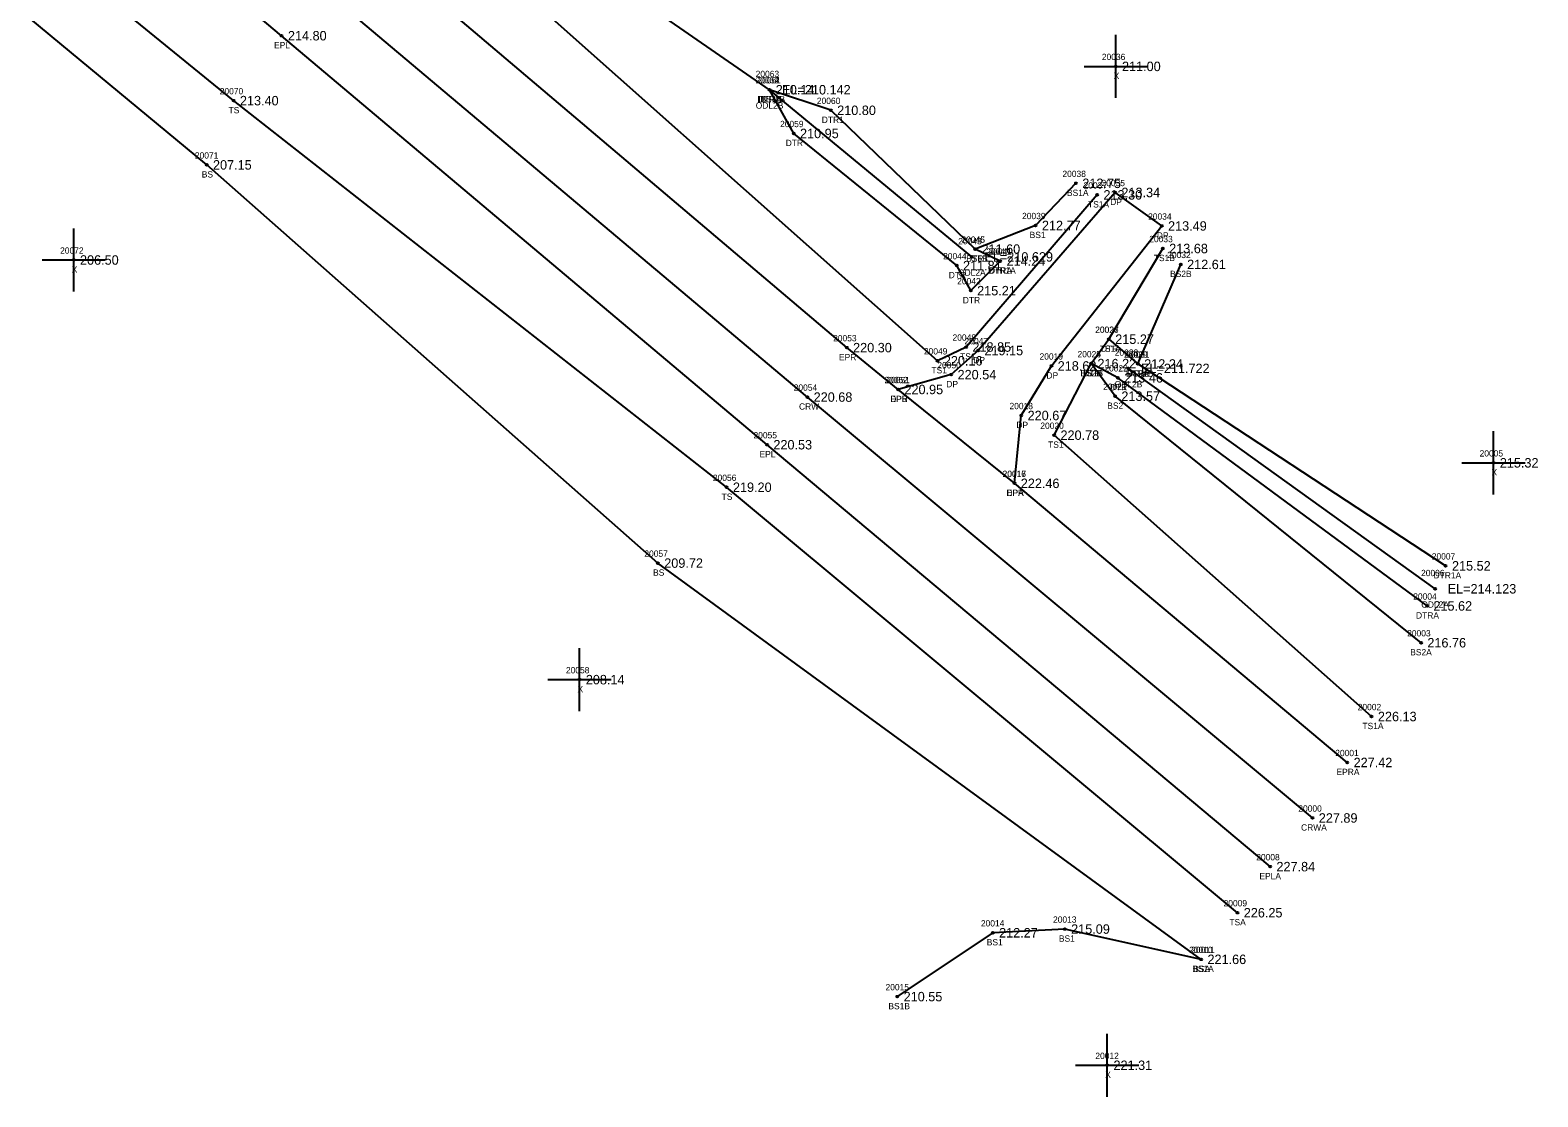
# Model space of a CAD drawing. Extents: x 2260230 to 2261304, y 1064626 to 1065587.
# Drawn here: x 2260916.2 to 2261155.1, y 1064774.4 to 1064943.4 of the extents above; entities that cross this region are included whole.
import ezdxf

# ---------------------------------------------------------------- set-up
doc = ezdxf.new("R2010")
doc.units = 0
for name, color, linetype in [('RD_DTM_BkLn1', 7, 'Continuous'), ('RD_DTM_BkLn2', 7, 'Continuous'), ('RD_DTM_BkLn_txCode', 7, 'Continuous'), ('RD_EX_Driveway', 7, 'Continuous'), ('RD_EX_Driveway_txCode', 7, 'Continuous'), ('RD_EX_H2O', 7, 'Continuous'), ('RD_EX_H2O_txCode', 7, 'Continuous'), ('RD_EX_Misc', 7, 'Continuous'), ('RD_EX_Misc_txCode', 7, 'Continuous'), ('RD_EX_Road', 7, 'Continuous'), ('RD_EX_Road_txCode', 7, 'Continuous'), ('RD_EX_TX_Driveway_ELEV', 7, 'Continuous'), ('RD_EX_TX_H2O_ELEV', 7, 'Continuous'), ('RD_EX_TX_Misc_ELEV', 7, 'Continuous'), ('RD_EX_TX_Road_ELEV', 7, 'Continuous'), ('RD_HC_Survey_ELEV', 7, 'Continuous'), ('RD_HC_Survey_txCode', 7, 'Continuous'), ('RD_SMD_Locator', 7, 'Continuous')]:
    doc.layers.add(name, color=color, linetype=linetype)

msp = doc.modelspace()

# ---------------------------------------------------------------- linework, layer by layer
at = {"layer": 'RD_DTM_BkLn1'}
msp.add_lwpolyline([(2261119.39, 1064818.57), (2261039.33, 1064885.27), (2260966.22, 1064946.78), (2260891.14, 1065010.3), (2260825.73, 1065065.53)], dxfattribs=at)
at = {"layer": 'RD_DTM_BkLn2'}
for p, q in [((2261087.13, 1064894.44), (2261095.68, 1064908.81)), ((2261091.72, 1064890.51), (2261098.52, 1064906.29))]:
    msp.add_line(p, q, dxfattribs=at)
for points in [[(2261107.5, 1064803.56), (2261026.54, 1064870.98), (2260948.4, 1064932.24), (2260874.38, 1064992.47), (2260842.04, 1065014.91), (2260817.83, 1065046.66), (2260820.04, 1065048.66), (2260815.22, 1065054.09)], [(2261101.75, 1064796.17), (2261015.65, 1064858.96), (2260944.13, 1064922.06), (2260868.1, 1064985.02), (2260817.12, 1065034.76), (2260812.18, 1065041.52), (2260806.25, 1065051.8)], [(2261085.26, 1064917.31), (2261064.5, 1064893.2), (2261059.96, 1064891.02), (2260979.07, 1064962.89), (2260952.45, 1064989.91), (2260955.15, 1064997.29), (2260970.81, 1065018.43)], [(2261033.32, 1064933.97), (2260984.04, 1064968.09), (2260958.89, 1064995.55), (2260960.53, 1065000.94), (2260972.35, 1065016.34)], [(2261081.91, 1064919.14), (2261075.51, 1064912.46), (2261065.93, 1064908.72)], [(2261128.76, 1064834.65), (2261078.45, 1064879.23), (2261084.31, 1064890.57)], [(2261136.6, 1064846.34), (2261088.1, 1064885.41), (2261084.31, 1064890.57)], [(2261101.75, 1064796.17), (2261080.14, 1064800.97), (2261068.72, 1064800.38), (2261053.59, 1064790.26)]]:
    msp.add_lwpolyline(points, dxfattribs=at)
at = {"layer": 'RD_EX_Driveway'}
msp.add_lwpolyline([(2261072.16, 1064871.6), (2261073.24, 1064882.35), (2261078.01, 1064890.2), (2261095.5, 1064912.38), (2261088.11, 1064917.69), (2261066.4, 1064892.64), (2261062.14, 1064888.82), (2261053.72, 1064886.47)], dxfattribs=at)
at = {"layer": 'RD_EX_H2O'}
for p, q in [((2261065.39, 1064907.48), (2261033.32, 1064933.97)), ((2261138.82, 1064854.89), (2261090.21, 1064889.81)), ((2261140.5, 1064858.52), (2261091.72, 1064890.51))]:
    msp.add_line(p, q, dxfattribs=at)
for points in [[(2261069.9, 1064906.82), (2261065.24, 1064902.13), (2261063, 1064906.1), (2261037.17, 1064927.04), (2261033.32, 1064933.97)], [(2261069.9, 1064906.82), (2261065.93, 1064908.72), (2261043.06, 1064930.71), (2261033.32, 1064933.97)], [(2261137.56, 1064852.17), (2261088.56, 1064888.32), (2261084.31, 1064890.57), (2261087.13, 1064894.44), (2261091.72, 1064890.51)]]:
    msp.add_lwpolyline(points, dxfattribs=at)
at = {"layer": 'RD_EX_Misc'}
for p, q in [((2261088.2, 1064932.67), (2261088.2, 1064942.67)), ((2261083.2, 1064937.67), (2261093.2, 1064937.67)), ((2260923.05, 1064901.99), (2260923.05, 1064911.99)), ((2260918.05, 1064906.99), (2260928.05, 1064906.99)), ((2261148.08, 1064869.85), (2261148.08, 1064879.85)), ((2261143.08, 1064874.85), (2261153.08, 1064874.85)), ((2261003.22, 1064835.49), (2261003.22, 1064845.49)), ((2260998.22, 1064840.49), (2261008.22, 1064840.49)), ((2261086.85, 1064774.38), (2261086.85, 1064784.38)), ((2261081.85, 1064779.38), (2261091.85, 1064779.38))]:
    msp.add_line(p, q, dxfattribs=at)
at = {"layer": 'RD_EX_Road'}
for points in [[(2261124.91, 1064827.37), (2261072.16, 1064871.6), (2261053.72, 1064886.47), (2261045.58, 1064893.1), (2260972.89, 1064954.76), (2260940.74, 1064982.39), (2260933.33, 1064988.76), (2260898.06, 1065017.6), (2260832.89, 1065075.07)], [(2261112.68, 1064810.86), (2261032.95, 1064877.72), (2260956.01, 1064942.53), (2260884.53, 1065002.6), (2260818.6, 1065058.26)]]:
    msp.add_lwpolyline(points, dxfattribs=at)
at = {"layer": 'RD_SMD_Locator'}
for centre in [(2260956.01, 1064942.53), (2261088.2, 1064937.67), (2260948.4, 1064932.24), (2261033.32, 1064933.97), (2261033.32, 1064933.97), (2261033.32, 1064933.97), (2261033.32, 1064933.97), (2261043.06, 1064930.71), (2261037.17, 1064927.04), (2260944.13, 1064922.06), (2261081.91, 1064919.14), (2261085.26, 1064917.31), (2261088.11, 1064917.69), (2261075.51, 1064912.46), (2261095.5, 1064912.38), (2261065.93, 1064908.72), (2261065.93, 1064908.72), (2261095.68, 1064908.81), (2260923.05, 1064906.99), (2261063, 1064906.1), (2261065.39, 1064907.48), (2261069.9, 1064906.82), (2261069.9, 1064906.82), (2261098.52, 1064906.29), (2261065.24, 1064902.13), (2261087.13, 1064894.44), (2261087.13, 1064894.44), (2261045.58, 1064893.1), (2261064.5, 1064893.2), (2261066.4, 1064892.64), (2261059.96, 1064891.02), (2261078.01, 1064890.2), (2261084.31, 1064890.57), (2261084.31, 1064890.57), (2261084.31, 1064890.57), (2261090.21, 1064889.81), (2261091.72, 1064890.51), (2261091.72, 1064890.51), (2261091.72, 1064890.51), (2261062.14, 1064888.82), (2261088.56, 1064888.32), (2261039.33, 1064885.27), (2261053.72, 1064886.47), (2261053.72, 1064886.47), (2261088.1, 1064885.41), (2261073.24, 1064882.35), (2261032.95, 1064877.72), (2261078.45, 1064879.23), (2261148.08, 1064874.85), (2261026.54, 1064870.98), (2261072.16, 1064871.6), (2261072.16, 1064871.6), (2261015.65, 1064858.96), (2261140.5, 1064858.52), (2261138.82, 1064854.89), (2261137.56, 1064852.17), (2261136.6, 1064846.34), (2261003.22, 1064840.49), (2261128.76, 1064834.65), (2261124.91, 1064827.37), (2261119.39, 1064818.57), (2261112.68, 1064810.86), (2261107.5, 1064803.56), (2261080.14, 1064800.97), (2261068.72, 1064800.38), (2261101.75, 1064796.17), (2261101.75, 1064796.17), (2261053.59, 1064790.26), (2261086.85, 1064779.38)]:
    msp.add_circle(centre, 0.15, dxfattribs=at)

# ---------------------------------------------------------------- texts
at = {"layer": 'RD_DTM_BkLn_txCode'}
for s, p in [('20064', (2261031.14, 1064934.97)), ('20070', (2260946.2, 1064933.24)), ('BS1A', (2261031.89, 1064931.97)), ('TS', (2260947.6, 1064930.24)), ('20071', (2260942.26, 1064923.06)), ('BS', (2260943.35, 1064920.06)), ('20038', (2261079.76, 1064920.14)), ('BS1A', (2261080.48, 1064917.14)), ('20037', (2261083.11, 1064918.31)), ('TS1A', (2261083.81, 1064915.31)), ('20039', (2261073.36, 1064913.46)), ('BS1', (2261074.57, 1064910.46)), ('20046', (2261063.75, 1064909.72)), ('20033', (2261093.52, 1064909.81)), ('BS1B', (2261064.51, 1064906.72)), ('TS1B', (2261094.24, 1064906.81)), ('20032', (2261096.37, 1064907.29)), ('BS2B', (2261096.82, 1064904.29)), ('20048', (2261062.34, 1064894.2)), ('20026', (2261084.94, 1064895.44)), ('20049', (2261057.81, 1064892.02)), ('TS1', (2261063.54, 1064891.2)), ('20024', (2261082.15, 1064891.57)), ('20025', (2261082.15, 1064891.57)), ('TS1A', (2261085.68, 1064892.44)), ('20031', (2261089.85, 1064891.51)), ('TS1', (2261059, 1064889.02)), ('BS2B', (2261082.61, 1064888.57)), ('TS1B', (2261082.87, 1064888.57)), ('BS2A', (2261090.01, 1064888.51)), ('20021', (2261086.22, 1064886.41)), ('BS2', (2261086.87, 1064883.41)), ('20020', (2261076.26, 1064880.23)), ('TS1', (2261077.49, 1064877.23)), ('20056', (2261024.36, 1064871.98)), ('TS', (2261025.74, 1064868.98)), ('20057', (2261013.5, 1064859.96)), ('BS', (2261014.88, 1064856.96)), ('20003', (2261134.4, 1064847.34)), ('BS2A', (2261134.88, 1064844.34)), ('20002', (2261126.56, 1064835.65)), ('TS1A', (2261127.31, 1064832.65)), ('20009', (2261105.3, 1064804.56)), ('20014', (2261066.84, 1064801.38)), ('20013', (2261078.27, 1064801.97)), ('TSA', (2261106.22, 1064801.56)), ('BS1', (2261067.77, 1064798.38)), ('BS1', (2261079.2, 1064798.97)), ('20010', (2261099.84, 1064797.17)), ('20011', (2261100.16, 1064797.17)), ('BS1A', (2261100.32, 1064794.17)), ('BSA', (2261100.49, 1064794.17)), ('20015', (2261051.72, 1064791.26)), ('BS1B', (2261052.18, 1064788.26))]:
    msp.add_text(s, height=1, dxfattribs=at).set_placement(p)
at = {"layer": 'RD_EX_Driveway_txCode'}
for s, p in [('20035', (2261085.95, 1064918.69)), ('DP', (2261087.33, 1064915.69)), ('20034', (2261093.34, 1064913.38)), ('DP', (2261094.72, 1064910.38)), ('20047', (2261064.25, 1064893.64)), ('20019', (2261076.13, 1064891.2)), ('20050', (2261059.94, 1064889.82)), ('DP', (2261065.63, 1064890.64)), ('20051', (2261051.85, 1064887.47)), ('DP', (2261061.36, 1064886.82)), ('DP', (2261077.23, 1064888.2)), ('DPB', (2261052.47, 1064884.47)), ('20018', (2261071.37, 1064883.35)), ('DP', (2261072.46, 1064880.35)), ('20017', (2261070.29, 1064872.6)), ('DPA', (2261070.89, 1064869.6))]:
    msp.add_text(s, height=1, dxfattribs=at).set_placement(p)
at = {"layer": 'RD_EX_H2O_txCode'}
for s, p in [('20063', (2261031.14, 1064935.97)), ('20062', (2261031.14, 1064934.97)), ('20061', (2261031.42, 1064934.97)), ('DTR1B', (2261031.41, 1064931.97)), ('DTRB', (2261031.58, 1064931.97)), ('20060', (2261040.84, 1064931.71)), ('ODL2B', (2261031.15, 1064930.97)), ('20059', (2261035.01, 1064928.04)), ('DTR1', (2261041.62, 1064928.71)), ('DTR', (2261035.9, 1064925.04)), ('20043', (2261063.24, 1064909.48)), ('20045', (2261063.77, 1064909.72)), ('20040', (2261067.7, 1064907.82)), ('20041', (2261068.03, 1064907.82)), ('20044', (2261060.85, 1064907.1)), ('DTR1', (2261064.5, 1064906.72)), ('DTR', (2261061.74, 1064904.1)), ('20042', (2261063.08, 1064903.13)), ('ODL2A', (2261063.21, 1064904.48)), ('DTR1A', (2261067.98, 1064904.82)), ('DTRA', (2261068.14, 1064904.82)), ('DTR', (2261063.97, 1064900.13)), ('20027', (2261084.97, 1064895.44)), ('20023', (2261082.15, 1064891.57)), ('DTR', (2261085.86, 1064892.44)), ('20028', (2261088.05, 1064891.81)), ('20030', (2261089.53, 1064891.51)), ('20029', (2261089.56, 1064891.51)), ('DTR', (2261083.04, 1064888.57)), ('20022', (2261086.4, 1064889.32)), ('DTR1B', (2261089.82, 1064888.51)), ('DTRB', (2261089.98, 1064888.51)), ('DTR', (2261087.29, 1064886.32)), ('ODL2B', (2261088.04, 1064886.81)), ('20007', (2261138.3, 1064859.52)), ('20006', (2261136.6, 1064856.89)), ('DTR1A', (2261138.58, 1064856.52)), ('20004', (2261135.36, 1064853.17)), ('DTRA', (2261135.8, 1064850.17)), ('ODL2A', (2261136.64, 1064851.89))]:
    msp.add_text(s, height=1, dxfattribs=at).set_placement(p)
at = {"layer": 'RD_EX_Misc_txCode'}
for s, p in [('20036', (2261086.01, 1064938.67)), ('X', (2261087.88, 1064935.67)), ('20072', (2260920.9, 1064907.99)), ('X', (2260922.74, 1064904.99)), ('20005', (2261145.88, 1064875.85)), ('X', (2261147.76, 1064872.85)), ('20058', (2261001.07, 1064841.49)), ('X', (2261002.91, 1064838.49)), ('20012', (2261084.98, 1064780.38)), ('X', (2261086.54, 1064777.38))]:
    msp.add_text(s, height=1, dxfattribs=at).set_placement(p)
at = {"layer": 'RD_EX_Road_txCode'}
for s, p in [('EPL', (2260954.81, 1064940.53)), ('20053', (2261043.42, 1064894.1)), ('EPR', (2261044.35, 1064891.1)), ('20052', (2261051.56, 1064887.47)), ('EPR', (2261052.49, 1064884.47)), ('20055', (2261030.8, 1064878.72)), ('EPL', (2261031.75, 1064875.72)), ('20016', (2261070.26, 1064872.6)), ('EPR', (2261070.93, 1064869.6)), ('20001', (2261123, 1064828.37)), ('EPRA', (2261123.2, 1064825.37)), ('20008', (2261110.48, 1064811.86)), ('EPLA', (2261110.98, 1064808.86))]:
    msp.add_text(s, height=1, dxfattribs=at).set_placement(p)
at = {"layer": 'RD_EX_TX_Driveway_ELEV'}
for s, p in [('213.34', (2261089.11, 1064916.94)), ('213.49', (2261096.5, 1064911.63)), ('219.15', (2261067.4, 1064891.89)), ('220.54', (2261063.14, 1064888.07)), ('218.62', (2261079.01, 1064889.45)), ('220.95', (2261054.72, 1064885.72)), ('220.67', (2261074.24, 1064881.6)), ('222.46', (2261073.16, 1064870.85))]:
    msp.add_text(s, height=1.5, dxfattribs=at).set_placement(p)
at = {"layer": 'RD_EX_TX_H2O_ELEV'}
for s, p in [('210.14', (2261034.32, 1064933.22)), ('210.14', (2261034.32, 1064933.22)), ('EL=210.142', (2261035.32, 1064933.22)), ('210.80', (2261044.06, 1064929.96)), ('210.95', (2261038.17, 1064926.29)), ('211.60', (2261066.93, 1064907.97)), ('211.81', (2261064, 1064905.35)), ('EL=210.629', (2261067.39, 1064906.73)), ('214.24', (2261070.9, 1064906.07)), ('214.24', (2261070.9, 1064906.07)), ('215.21', (2261066.24, 1064901.38)), ('215.27', (2261088.13, 1064893.69)), ('216.22', (2261085.31, 1064889.82)), ('EL=211.722', (2261092.21, 1064889.06)), ('212.24', (2261092.72, 1064889.76)), ('212.24', (2261092.72, 1064889.76)), ('213.46', (2261089.56, 1064887.57)), ('215.52', (2261141.5, 1064857.77)), ('EL=214.123', (2261140.82, 1064854.14)), ('215.62', (2261138.56, 1064851.42))]:
    msp.add_text(s, height=1.5, dxfattribs=at).set_placement(p)
at = {"layer": 'RD_EX_TX_Misc_ELEV'}
for s, p in [('211.00', (2261089.2, 1064936.92)), ('213.40', (2260949.4, 1064931.49)), ('210.14', (2261034.32, 1064933.22)), ('207.15', (2260945.13, 1064921.31)), ('212.75', (2261082.91, 1064918.39)), ('213.30', (2261086.26, 1064916.56)), ('212.77', (2261076.51, 1064911.71)), ('211.60', (2261066.93, 1064907.97)), ('213.68', (2261096.68, 1064908.06)), ('206.50', (2260924.05, 1064906.24)), ('212.61', (2261099.52, 1064905.54)), ('215.27', (2261088.13, 1064893.69)), ('220.16', (2261060.96, 1064890.27)), ('218.85', (2261065.5, 1064892.45)), ('216.22', (2261085.31, 1064889.82)), ('216.22', (2261085.31, 1064889.82)), ('212.24', (2261092.72, 1064889.76)), ('213.57', (2261089.1, 1064884.66)), ('220.78', (2261079.45, 1064878.48)), ('215.32', (2261149.08, 1064874.1)), ('219.20', (2261027.54, 1064870.23)), ('209.72', (2261016.65, 1064858.21)), ('216.76', (2261137.6, 1064845.59)), ('208.14', (2261004.22, 1064839.74)), ('226.13', (2261129.76, 1064833.9)), ('226.25', (2261108.5, 1064802.81)), ('212.27', (2261069.72, 1064799.63)), ('215.09', (2261081.14, 1064800.22)), ('221.66', (2261102.75, 1064795.42)), ('221.66', (2261102.75, 1064795.42)), ('210.55', (2261054.59, 1064789.51)), ('221.31', (2261087.85, 1064778.63))]:
    msp.add_text(s, height=1.5, dxfattribs=at).set_placement(p)
at = {"layer": 'RD_EX_TX_Road_ELEV'}
for s, p in [('214.80', (2260957.01, 1064941.78)), ('220.30', (2261046.58, 1064892.35)), ('220.95', (2261054.72, 1064885.72)), ('220.53', (2261033.95, 1064876.97)), ('222.46', (2261073.16, 1064870.85)), ('227.42', (2261125.91, 1064826.62)), ('227.84', (2261113.68, 1064810.11))]:
    msp.add_text(s, height=1.5, dxfattribs=at).set_placement(p)
at = {"layer": 'RD_HC_Survey_ELEV'}
for s, p in [('220.68', (2261040.33, 1064884.52)), ('227.89', (2261120.39, 1064817.82))]:
    msp.add_text(s, height=1.5, dxfattribs=at).set_placement(p)
at = {"layer": 'RD_HC_Survey_txCode'}
for s, p in [('20054', (2261037.17, 1064886.27)), ('CRW', (2261038.01, 1064883.27)), ('20000', (2261117.15, 1064819.57)), ('CRWA', (2261117.58, 1064816.57))]:
    msp.add_text(s, height=1, dxfattribs=at).set_placement(p)

doc.saveas('drawing.dxf')
